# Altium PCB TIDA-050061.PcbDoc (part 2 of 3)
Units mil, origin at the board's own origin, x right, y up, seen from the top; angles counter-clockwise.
Board outline 3950.94 x 4411.21 mil, 8 copper layers (Top Layer, Layer 1, Layer 2, Layer 3, Layer 4, Layer 5, Layer 6, Bottom Layer), stack 61.2 mil thick; 178 components, 34 nets, 398 pads, 112 vias.
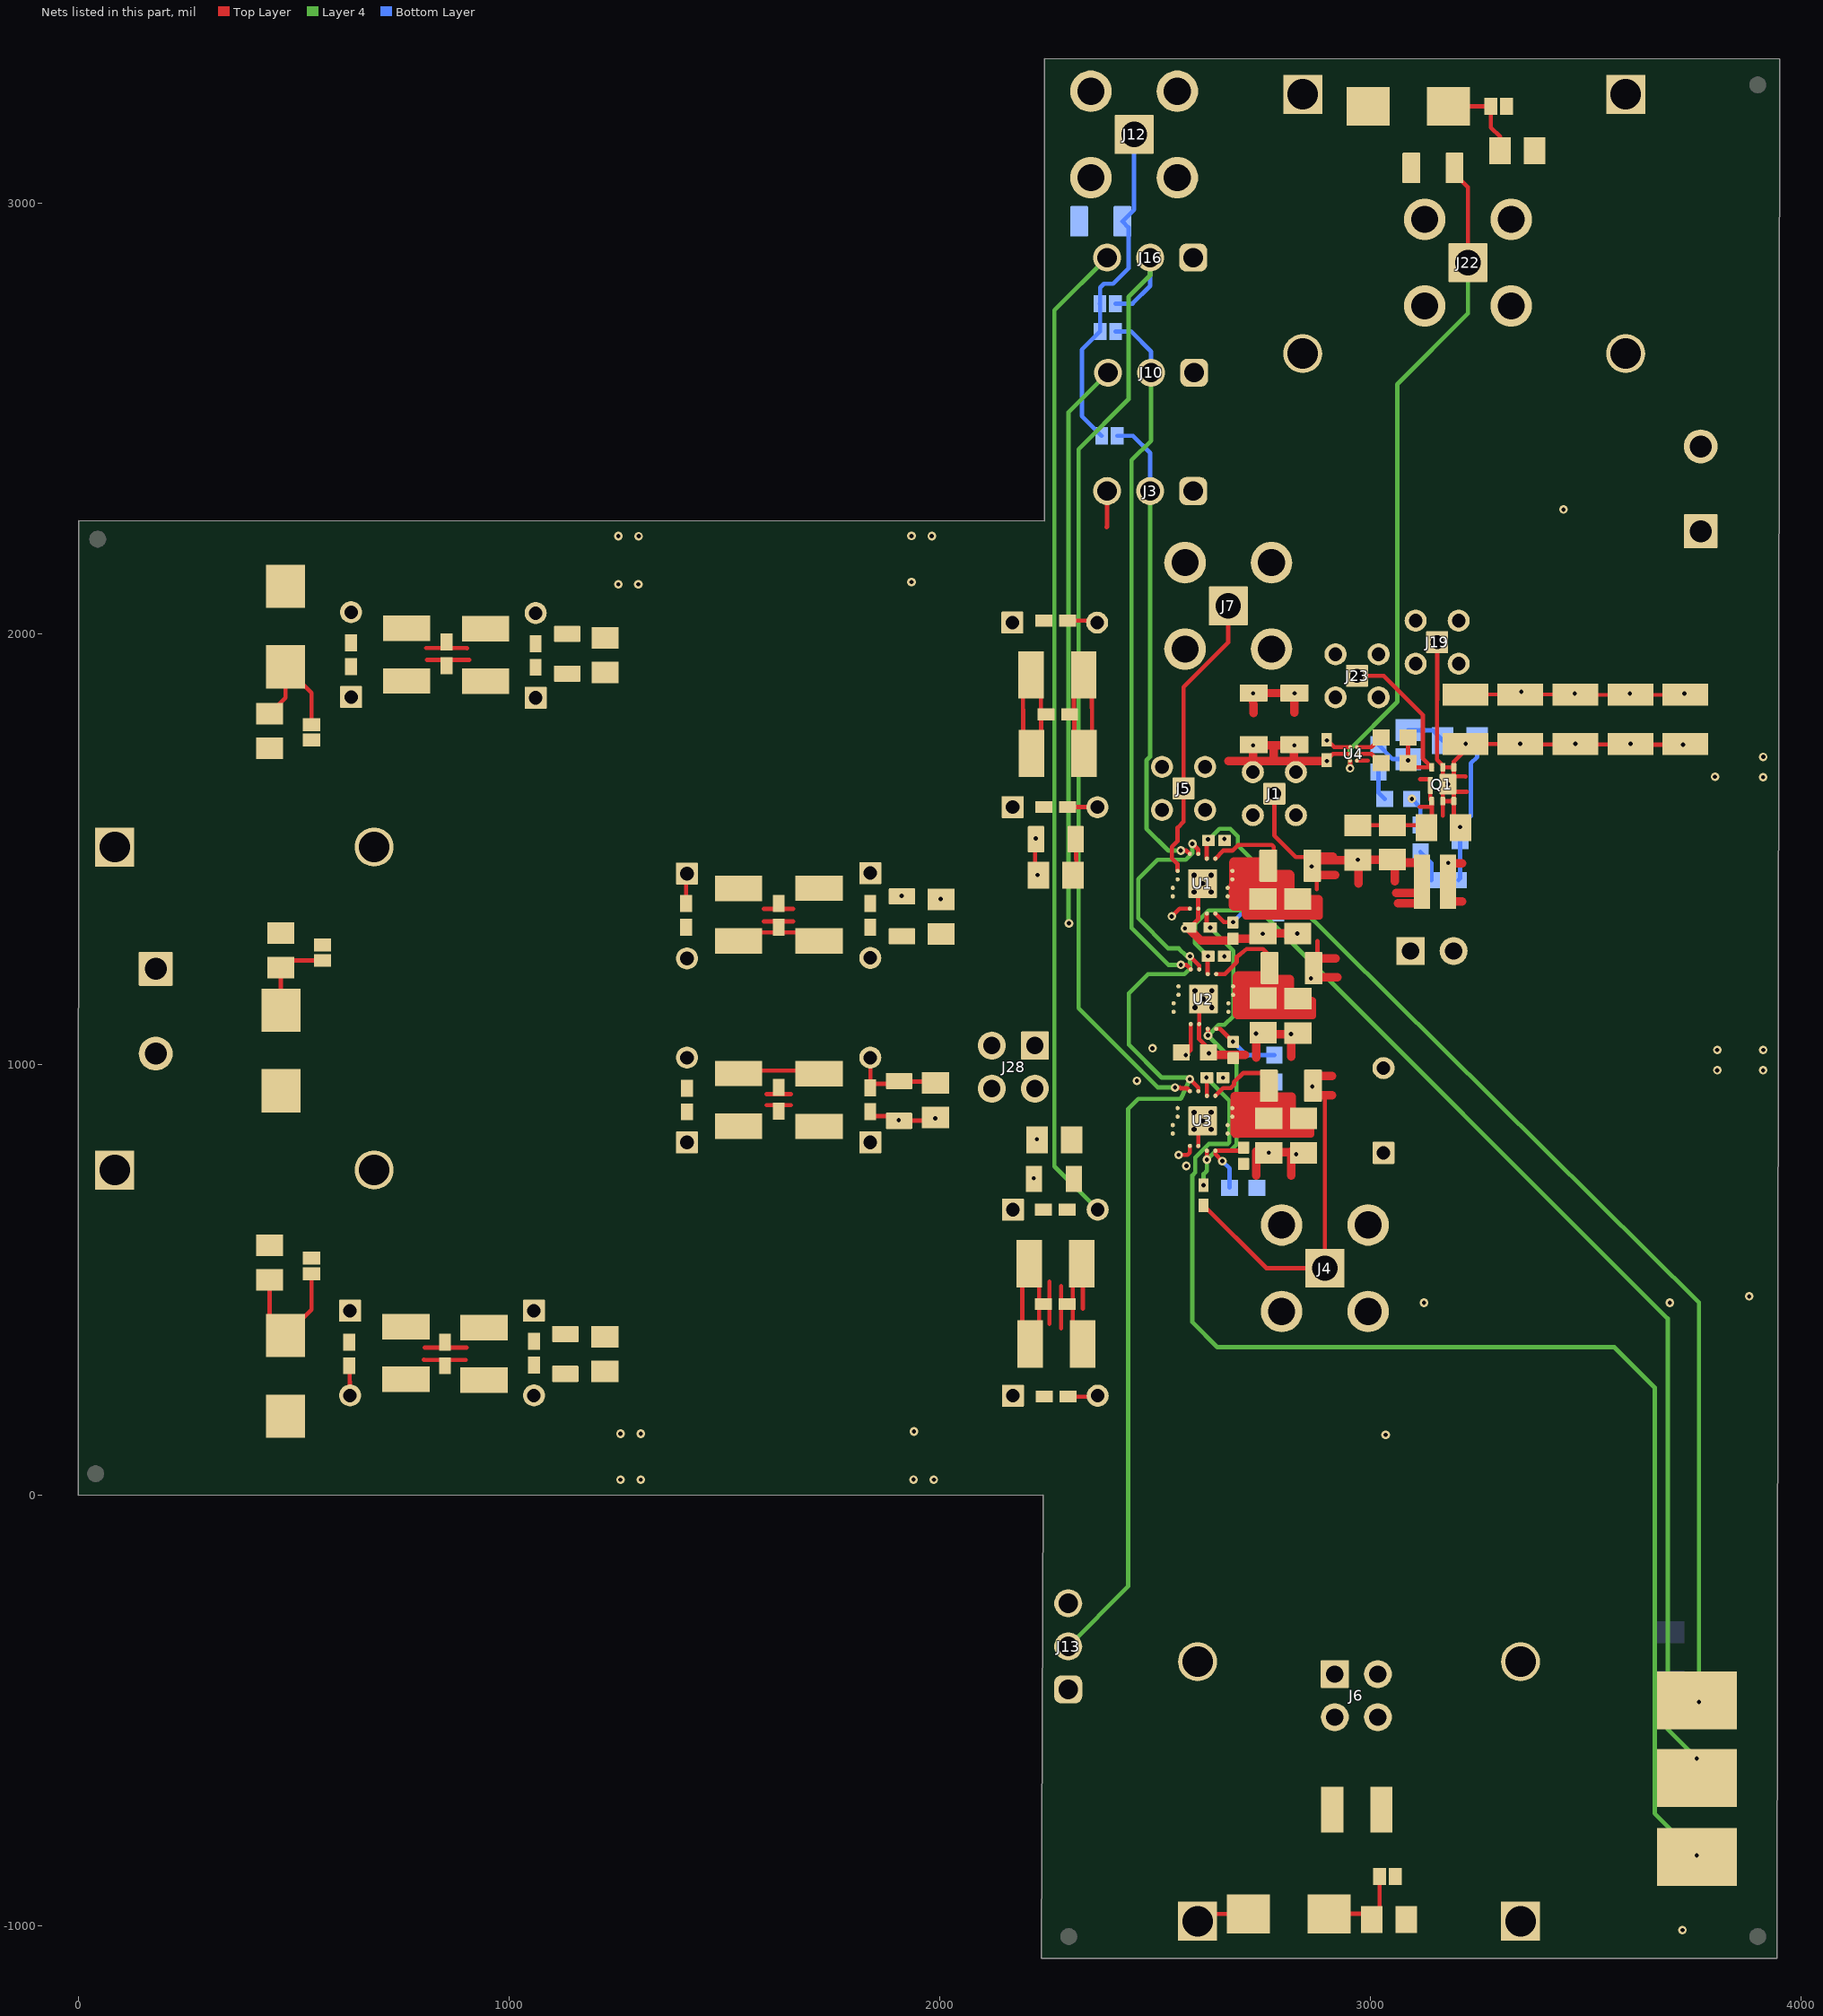
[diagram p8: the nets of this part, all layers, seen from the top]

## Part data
C1 C28 C29 C30 C31 C48 C49 C56 C57 C66 C67 C68 C69: library part CMP-0093206-1, "Cap Aluminum Polymer 560uF 20VDC 20% (10 X 13mm) Radial 5mm 0.012 Ohm 1700mA 1000h 125C", Digikey Part Number=P122095-ND, Leakage Current=2240uA, Manufacturer=Panasonic, Mouser Part Number=667-20SEF560M, Operating Temperature Range="-55°C to +125°C", Tolerance_%=20%, ValueDisplayed=560uF
C2: library part CMP-0081639-1, "CAP, CERM, 10 µF, 35 V,+/- 10%, X7R, 1210", Cap_Case=1210, Manufacturer=MuRata, Supplier Part Number 1=GRM32ER7YA106KA12K-ND, TempCo=X7R, Tolerance_%=10%, Value1="0.001 ohm", Value2=35V, ValueDisplayed=10µF
C3: library part CMP-0006949-4, "CAP, CERM, 4.7 uF, 10 V, +/- 10%, X5R, 0603", Cap_Case=0603, Manufacturer=Kemet, Supplier Part Number 1=399-5503-1-ND, TempCo=X5R, Tolerance_%=10%, Value1="0.006 ohm", Value2=10V, ValueDisplayed=4.7uF
C4 C5 C7 C11 C15: library part CMP-0008377-2, "CAP, CERM, 22 uF, 10 V, +/- 20%, X7R, 0805", Cap_Case=0805, Manufacturer=MuRata, Supplier Part Number 1=81-GRM21BZ71A226ME5L, TempCo=X7R, Tolerance_%=20%, Value1=Unknown, Value2=10V, ValueDisplayed=22uF
C6 C20 C26 C45 C64: library part CMP-0011645-1, "CAP, TA, 10 uF, 25 V, +/- 20%, 0.5 ohm, SMD", Cap_Case=C, Manufacturer=AVX, Supplier Part Number 1=478-1763-1-ND, Tolerance_%=20%, Value1="0.5 ohm", Value2=25V, ValueDisplayed=10uF
C8 C12 C16: library part CMP-0080705-2, "CAP, CERM, 2.2 µF, 25 V,+/- 10%, X7R, 0805", Cap_Case=0805, Manufacturer="Taiyo Yuden", Supplier Part Number 1=587-2991-1-ND, TempCo=X7R, Tolerance_%=10%, Value2=25V, ValueDisplayed=2.2µF
C9 C13 C17: library part CMP-0093200-1, "1µF ±10% 10V Ceramic Capacitor X7R 0402 (1005 Metric)", Digikey Part Number=2571-GMC04X7R105K10NTTR-ND, Manufacturer="Cal-Chip Electronics", Operating Temperature Range="-55°C to +125°C", TempCo=15%, Temperature Characteristic=X7R, Tolerance_%=10%, ValueDisplayed=1uF
C10 C14 C18: library part CMP-0064936-1, "CAP, CERM, 4.7 uF, 16 V,+/- 10%, X7R, 0603", Cap_Case=0603, Manufacturer=MuRata, TempCo=X7R, Tolerance_%=10%, Value1=Unknown, Value2=16V, ValueDisplayed=4.7uF
C19: library part CMP-0008040-1, "CAP, CERM, 1 pF, 100 V, +/- 5%, C0G/NP0, 0805", Cap_Case=0805, Manufacturer=MuRata, PartNumber=GQM2195C2A1R0CB01D, Supplier Part Number 1=490-3586-1-ND, TempCo=C0G/NP0, Tolerance_%=5%, Value1=Unknown, Value2=100V, ValueDisplayed=1pF
C21: library part CMP-0006297-2, "CAP, CERM, 0.1 uF, 50 V, +/- 10%, X7R, 0402", Cap_Case=0402, Manufacturer=TDK, Supplier Part Number 1=445-5932-1-ND, TempCo=X7R, Tolerance_%=10%, Value1="0.039064 ohm", Value2=50V, ValueDisplayed=0.1uF
C22 C23: library part CMP-0093201-1, "10 µF ±10% 50V Ceramic Capacitor X7R 1206 (3216 Metric)", Manufacturer="Cal-Chip Electronics", Operating Temperature Range="-55°C to +125°C", TempCo=15%, Temperature Characteristic=X7R, Tolerance_%=10%, ValueDisplayed=10uF
C24 C25: library part CMP-0006723-4, "CAP, CERM, 1000 pF, 100 V, +/- 5%, X7R, 0603", Cap_Case=0603, Manufacturer=AVX, Supplier Part Number 1=478-3698-1-ND, TempCo=X7R, Tolerance_%=5%, Value1="0.276 ohm", Value2=100V, ValueDisplayed=1000pF
C27 C38 C46 C47 C65 C76: library part CMP-0090082-1, "Cap Ceramic 4.7uF 50V X7R 10% Pad SMD 0805 +125°C Automotive T/R", Manufacturer="TDK Corporation", Operating Temperature Range="-55°C to +125°C", TempCo=15%, Temperature Characteristic=X7R, Tolerance_%=0.1%, ValueDisplayed=4.7uF
C32 C33 C39 C40 C50 C51 C58 C59 C70 C71 C77 C78: library part CMP-0080066-1, "CAP, CERM, 22 µF, 25 V,+/- 10%, X7R, 1210", Cap_Case=1210, Manufacturer="Samsung Electro-Mechanics", Supplier Part Number 1=1276-3391-1-ND, TempCo=X7R, Tolerance_%=10%, Value2=25V, ValueDisplayed=22µF
C34 C41 C52 C60 C72 C79: library part CMP-0079630-1, "CAP, CERM, 1 µF, 16 V,+/- 10%, X7R, AEC-Q200 Grade 1, 0805", Cap_Case=0805, Manufacturer=Kemet, Supplier Part Number 1=399-6930-1-ND, TempCo=X7R, Tolerance_%=10%, Value2=16V, ValueDisplayed=1µF
C35 C36 C37 C42 C43 C44 C53 C54 C55 C61 C62 C63 C73 C74 C75 C80 C81 C82: library part CMP-0860570-1, "CAP, CERM, 0.1 µF, 50 V,+/- 20%, X7R, 0402", Cap_Case=0402, Manufacturer="Taiyo Yuden", TempCo=X7R, Tolerance_%=20%, Value2=50V, ValueDisplayed=0.1µF
FID1 FID2 FID3 FID4 FID5 FID6 FID7 FID8 FID9 FID10: library part CMP-0077181-1, "Fiducial mark.  There is nothing to buy or mount.", Manufacturer=N/A
J1 J5 J19 J23: library part CMP-0096285-1, "MMCX Connector Jack, Female Socket 50Ohm Through Hole Solder", Dielectric Material=TEFLON, Digikey Part Number=2057-RF12-07H-T-00-50-G-ND, Manufacturer="Adam Tech", Operating Temperature Range=to
J2 J27: library part CMP-0055393-3, "Standard Banana Jack, insulated, 10A, red", Manufacturer="DEM Manufacturing", Supplier Part Number 1=30M0087
J3 J10 J13 J16: library part CMP-0054796-2, "Header, 2.54 mm, 3x1, Gold, TH", Color=Black, Manufacturer="Wurth Elektronik", Supplier Part Number 1=732-5316-ND
J4 J7 J12 J22: library part CMP-0096117-1, "SMA Connector Jack, Female Socket 50Ohm Through Hole Solder", Dielectric Material=PTFE, Digikey Part Number=2057-RF2-04A-T-00-50-G-ND, Frequency_Fixed=6GHz, Manufacturer="Adam Tech", Operating Temperature Range="-65°C to +165°C", Voltage_V=500V
J6 J28: library part CMP-0075404-1, "Header, 100mil, 2x2, Gold, TH", Color=Black, Current_A=6.3A, Manufacturer=Samtec, Supplier Part Number 1=SAM1028-02-ND, Voltage_V=550V
J8 J14 J15 J17 J20 J24 J26 J29 J32: library part CMP-0003883-1, "Jumper, SMT", Manufacturer=Any
J9 J31: library part CMP-0055389-3, "Standard Banana Jack, insulated, 10A, black", Manufacturer="DEM Manufacturing", Supplier Part Number 1=45M6896
J11 J30: library part CMP-0087503-1, "TERM BLK 2POS SIDE ENTRY 5MM PCB", Current_A=16A, Manufacturer="Würth Elektronik", Voltage_V=300V
J18: library part CMP-0054566-1, "Header, 100mil, 2x1, Gold, TH", Color=Black, Current_A=3A, Manufacturer="Sullins Connector Solutions", Supplier Part Number 1=S1011E-02-ND, Voltage_V=1.8kV
J21: library part CMP-0055393-3, "Standard Banana Jack, insulated, 10A, red", Manufacturer="DEM Manufacturing", PartNumber=571-0500, Supplier Part Number 1=30M0087
J25: library part CMP-0055389-3, "Standard Banana Jack, insulated, 10A, black", Manufacturer="DEM Manufacturing", PartNumber=571-0100, Supplier Part Number 1=45M6896
LOGO1: library part CMP-0074837-1, "IEC 61010-1 Hot Surface Warning"
Logo2: library part CMP-0074844-1
Logo4: library part CMP-0074847-1, "FCC_disclaimer"
Logo5: library part CMP-0074769-1
MP1: library part CMP-0095762-1, "Thermal Pad White 19.05mm x 6.35mm Rectangular Adhesive - Both Sides", Digikey Part Number=19.05MM-6.35MM-25-8810-ND, Manufacturer=3M, Operating Temperature Range=to
MP2: library part CMP-0096629-1, "Heatsink, 46 K/W, 19x6.3x4.8 mm, black anodized", Digikey Part Number=AE10818-ND, Manufacturer="Assmann WSW Components", Natural Thermal Resistance=46°C/W, Operating Temperature Range=to
Q1: library part CMP-0095537-1, "40 V optiMOS Power Transistor, Surface Mount 6-PQFN Dual (2x2)", Digikey Part Number=448-ISK024NE2LM5AULA1CT-ND, Drain To Source Breakdown Voltage=25V, Input Capacitace At Vds="960pF @ 12V", Manufacturer=Infineon, Mouser Part Number=726-ISK024NE2LM5AULA, Operating Temperature Range="-55°C to +150°C", Power_W=2.1W, Pulse Drain Current=221A, Typ Forward Diode Voltage=0.81V
R1 R4 R7: library part CMP-0095593-1, "Fixed Resistor, Metal Alloy, 1W, 0.0025ohm, 1% +/-Tol, 50ppm/Cel, Surface Mount, 1206", Manufacturer=Welwyn, Mouser Part Number=756-ULR1S-R0025FT2, Operating Temperature Range="-55°C to +170°C", Power_W=1W, TempCo=50ppm/°C, Tolerance_%=1%
R2 R5 R8: library part CMP-0092204-1, "100 kOhms ±1% 0.063W, 1/16W Chip Resistor 0402 (1005 Metric)  Thick Film", Digikey Part Number=541-3960-1-ND, Manufacturer=Vishay, Mouser Part Number=71-CRCW0402100KFKEDC, Operating Temperature Range="-55°C to +155°C", Power_W=63mW, TempCo=100ppm/°C, Tolerance_%=1%
R3 R24 R26 R27 R28: library part CMP-0074786-1, "RES, 1.00, 1%, 0.333 W, AEC-Q200 Grade 1, 0805", Manufacturer=Panasonic, Power_W=333mW, Supplier Part Number 1=P17499CT-ND, TempCo="200 ppm/C", Tolerance_%=1%, Value2=0.333W, Value_Code=1R00, ValueDisplayed=1.00
R6 R10: library part CMP-0026414-2, "RES, 4.99 k, 1%, 0.063 W, AEC-Q200 Grade 0, 0402", Manufacturer=Vishay-Dale, Power_W=63mW, Supplier Part Number 1=541-4.99KLCT-ND, TempCo="100 ppm/C", Tolerance_%=1%, Value2=0.063W, Value_Code=4k99, ValueDisplayed=4.99k
R9 R25: library part CMP-0093196-1, "RES Thick Film, 49.9Ω, 1%, 0.75W, 100ppm/°C, 1206", Manufacturer="Vishay Dale", Operating Temperature Range="-55°C to +155°C", Power_W=750mW, TempCo=100ppm/°C, Tolerance_%=1%
R11: library part CMP-0084633-1, "RES, 0.005, 1%, 0.5 W, AEC-Q200 Grade 0, 1206", Manufacturer=Vishay-Dale, Power_W=500mW, TempCo="110 ppm/C", Tolerance_%=1%, Value2=0.5W, Value_Code=5L000, ValueDisplayed=0.005
R12: library part CMP-0015056-3, "RES, 0.05, 1%, 1 W, AEC-Q200 Grade 0, 0612", Manufacturer=Panasonic, Power_W=1W, Supplier Part Number 1=P18935CT-ND, TempCo="150 ppm/C", Tolerance_%=1%, Value_Code=R050, ValueDisplayed=0.05
R13 R14 R15 R16 R17: library part CMP-0082786-1, "RES, 154, 1%, 0.5 W, 1210", Manufacturer=Yageo, Power_W=500mW, TempCo="100 ppm/C", Tolerance_%=1%, Value2=0.5W, Value_Code=154R, ValueDisplayed=154
R18: library part CMP-0020616-3, "RES, 0, 5%, 0.125 W, AEC-Q200 Grade 0, 0805", Manufacturer=Panasonic, Power_W=125mW, Supplier Part Number 1=P0.0ACT-ND, TempCo="600 ppm/C", Tolerance_%=5%, Value2=0.125W, Value_Code=0000, ValueDisplayed=0
R19 R20: library part CMP-0022906-5, "RES, 20.0 k, 1%, 0.1 W, 0603", Manufacturer=Yageo, Power_W=100mW, Supplier Part Number 1=311-20.0KHRCT-ND, TempCo="100 ppm/C", Tolerance_%=1%, Value2=0.1W, Value_Code=20k0, ValueDisplayed=20.0k
R21: library part CMP-0021519-3, "RES, 1.00 k, 1%, 0.125 W, AEC-Q200 Grade 0, 0805", Manufacturer=Panasonic, Power_W=125mW, Supplier Part Number 1=P1.00KCCT-ND, TempCo="100 ppm/C", Tolerance_%=1%, Value2=0.125W, Value_Code=1k00, ValueDisplayed=1.00k
R22 R23: library part CMP-0023343-3, "RES, 0, 1%, 0.1 W, AEC-Q200 Grade 0, 0603", Manufacturer="Stackpole Electronics Inc", Power_W=100mW, Supplier Part Number 1=RMCF0603ZT0R00CT-ND, TempCo=ppm/C, Tolerance_%=1%, Value2=0.1W, Value_Code=0
SH-J1 SH-J2 SH-J3 SH-J4: library part CMP-0003623-3, "Shunt, 100mil, Gold plated, Black", Alternate Manufacturer=3M, Alternate PartNumber=969102-0000-DA, Manufacturer=Samtec, Supplier Part Number 1=SAM8858-ND
TP1 TP2 TP3: library part CMP-0055153-1, "Test Point, Compact, SMT", Manufacturer=Keystone, Supplier Part Number 1=36-5016TR-ND
U1 U2 U3: library part CMP-0090637-2, "5-A, Low-VIN (0.7V), Low-Noise, High-Accuracy, Ultra-Low Dropout (LDO) Voltage Regulator", Dropout Voltage=100mV, Manufacturer="Texas Instruments", Max Supply Voltage=6V, Min Supply Voltage=700mV, Nominal Supply Current=10mA, Operating Temperature Range="-40°C to +125°C", Output Voltage=0.5-5.2V
U4: library part CMP-0084842-1, "5V, 7A/5A Low Side GaN Driver With 60MHz/1ns Speed, YFF0006AEAE (DSBGA-6)", Alternate Manufacturer="Texas Instruments", Alternate PartNumber=LMG1020YFFT, Operating Temperature Range="-40 to 125 C", Rating=Catalog
ZZ1: library part CMP-0077236-1
ZZ2: library part CMP-0077237-1
ZZ3: library part CMP-0077238-1
ZZ4 ZZ5 ZZ6 ZZ7 ZZ8: library part CMP-0077238-1, "The tab route width shall be between 80 mils and 120 mils"

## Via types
v1: diameter 20, hole 10, Top Layer to Bottom Layer, 97 vias
v2: diameter 23.62, hole 11.81, Top Layer to Bottom Layer, 15 vias

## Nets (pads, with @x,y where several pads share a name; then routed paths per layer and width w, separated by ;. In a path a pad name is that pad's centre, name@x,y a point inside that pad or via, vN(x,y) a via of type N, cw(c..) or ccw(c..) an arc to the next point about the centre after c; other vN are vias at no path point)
BIAS: C2.1 C3.1 C6.1 J2.1 J2.2 J6.1 J6.3 R2.1 R5.1 R8.1 U1.5 U2.5 U3.5 | length 268
  Top Layer w10: v1(2539.12,1344.04) 2557.07,1361.99 U1.5@2581.01,1361.99 ; v1(2555.13,790.07) 2575.98,790.07 2581.35,795.45 U3.5@2581.35,811.19 ; v1(2571.74,1022.08) 2583.2,1033.54 U2.5@2583.2,1094.01 ; J2.1@2589.99,-972.33 C6.1@2687.79,-972.4
  other v1: 2658.06,969.37 2661.36,1251.35 2661.53,1523.86
CP_EN: J13.2 U1.15 U2.15 U3.15 | length 2502.2
  Top Layer w10: v1(2580.96,966.35) 2601.04,946.27 U3.15@2601.04,938.16 U3.15@2600.78,938.42 ; v1(2581.38,1251.59) 2602.89,1230.09 U2.15@2602.89,1220.98 ; v1(2587.1,1512.63) 2600.69,1499.03 2600.69,1488.96 U1.15@2600.14,1489.5
  Layer 4 w10: J13.2@2298.69,-351.13 2437.86,-211.96 2437.86,896.81 2461.49,920.44 2559.95,920.44 v1(2580.96,966.35) 2577.59,969.72 2560.15,969.72 2516.03,969.61 2439.61,1046.03 2439.61,1165.52 2483.41,1209.32 2568.61,1209.92 2581.38,1222.7 v1(2581.38,1251.59) 2573.64,1251.59 2555.42,1269.81 2530.69,1269.81 2461.49,1339.81 2461.49,1430.8 2506.44,1475.75 2571.83,1475.75 2587.1,1491.01 v1(2587.1,1512.63)
EN_1: J3.2 J14.1 U1.16 | length 1094.1
  Top Layer w10: v1(2559.95,1496.98) 2572.98,1496.98 U1.16@2581.01,1488.96
  Layer 4 w10: J3.2@2488.97,2331.8 2488.97,1714.9 2480.41,1706.34 2480.41,1547.63 2531.06,1496.98 v1(2559.95,1496.98)
  Bottom Layer w10: J14.1@2412.37,2460 2449.24,2460 2488.97,2420.27 J3.2@2488.97,2331.8
EN_2: J10.2 J15.1 U2.16 | length 1636.4
  Top Layer w10: v1(2560.15,1231.44) 2572.74,1231.44 U2.16@2583.2,1220.98
  Layer 4 w10: J10.2@2491.25,2606.66 2491.25,2448.76 2445.86,2403.36 2445.86,1316.85 2531.26,1231.44 v1(2560.15,1231.44)
  Bottom Layer w10: J15.1@2408.69,2702.4 2444.22,2702.4 2491.25,2655.37 J10.2@2491.25,2606.66
EN_3: J16.2 J17.1 U3.16 | length 2302.7
  Top Layer w10: 2558.02,946.78 2559.93,944.87 2574.65,944.87 U3.16@2581.35,938.16
  Layer 4 w10: J16.2@2488.97,2873.82 2488.97,2832.64 2438.97,2782.64 2438.97,2545 2322.61,2428.64 2322.61,1131.03 2506.86,946.78 v1(2546.89,946.78)
  Bottom Layer w10: J17.1@2408.19,2767.07 2448.03,2767.07 2488.97,2808.01 J16.2@2488.97,2873.82
GND: C1.1 C2.2 C3.2 C4.2 C5.2 C7.2 C8.2 C9.1 C10.2 C11.2 C12.2 C13.1 C14.2 C15.2 C16.2 C17.1 C18.2 C21.2 C22.1 C23.1 C24.2 C25.2 C27.1 C28.1 C29.1 C30.1 C31.1 C32.2 C33.2 C34.2 C35.2 C36.2 C37.2 C38.1 C39.2 C40.2 C41.2 C42.2 C43.2 C44.2 C46.1 C47.1 C48.1 C49.1 C50.2 C51.2 C52.2 C53.2 C54.2 C55.2 C56.1 C57.1 C58.2 C59.2 C60.2 C61.2 C62.2 C63.2 C65.1 C66.1 C67.1 C68.1 C69.1 C70.2 C71.2 C72.2 C73.2 C74.2 C75.2 C76.1 C77.2 C78.2 C79.2 C80.2 C81.2 C82.2 J1.2 J1.3 J1.4 J1.5 J3.1 J4.2 J4.3 J4.4 J4.5 J5.2 J5.3 J5.4 J5.5 J6.2 J6.4 J7.2 J7.3 J7.4 J7.5 J8.1 J9.1 J9.2 J10.1 J11.2 J12.2 J12.3 J12.4 J12.5 J13.1 J16.1 J19.2 J19.3 J19.4 J19.5 J22.2 J22.3 J22.4 J22.5 J23.2 J23.3 J23.4 J23.5 J24.1 J25.1 J25.2 J26.1 J28.2 J28.4 J29.1 J30.1 J31.1 J31.2 J32.1 Q1.4 R3.1 R9.1 R10.1 R21.1 R24.1 R25.1 R26.1 R27.1 R28.1 U1.6 U1.17 U2.6 U2.17 U3.6 U3.17 U4.B1 U4.C2 | length 3021.3
  Top Layer w10: 803.86,342.57 901.65,342.49 ; 809.47,1939.56 907.36,1939.41 ; C57.1@1411.18,1438.19 C63.2@1411.4,1371.75 ; 1592.15,1361.37 1660.05,1361.24 ; 1598.04,905.64 1654.55,905.64 ; C53.2@1836.06,880.2 C46.1@1892.57,880.2 ; C46.1@1921.93,870.06 C52.2@1978.45,870.06 ; C70.2@2192.16,387.63 C71.2@2192.24,485.43 ; C33.2@2193.68,1875.05 2194.3,1777.97 ; C27.1@2221.6,1518.76 C34.2@2222.21,1421.68 ; C70.2@2231.16,394.87 C71.2@2231.24,492.67 ; C33.2@2235.46,1861.61 C32.2@2236.08,1764.53 ; 2255.04,398.13 2255.12,495.93 ; R10.1@2581.01,1318.16 2600.69,1337.85 2600.69,1361.99 2600.69,1390.53 U1.17@2590.85,1400.37 ; U3.6@2599.93,810.09 U3.6@2601.04,811.19 2601.04,859.42 v2(2610.88,869.27) ; U2.6@2601.94,1093.06 U2.6@2602.69,1093.82 ; v2(2612.73,1152.08) 2602.89,1142.24 U2.6@2602.89,1094.01 ; C3.2@2637.44,1028.42 2633.26,1028.42 2602.69,1058.98 U2.6@2602.69,1093.82 ; v1(2728.14,1741.22) C22.1@2728.19,1741.26 ; C7.2@2738.13,1292.26 C7.2@2750.48,1304.6 ; C21.2@2899.21,1706.91 2913.7,1721.4 U4.B1@2953.46,1721.4 ; U4.C2@2969.21,1705.65 2994.79,1705.65 2994.9,1705.77 ; C5.2@2974.13,1555.75 3056.27,1555.75 3121.87,1555.75 3128.55,1549.07 3142.96,1563.48 Q1.4@3142.96,1611.62 3139.61,1614.96 Q1.4@3139.61,1648.03 ; 3114.79,1598.69 3139.57,1598.56 ; 3115.44,1662.74 Q1.4@3140.22,1662.6 ; U2.6@2602.69,1093.82 2602.69,1094.01 U2.6@2602.89,1094.01 ; U2.6@2602.69,1093.82 U2.6@2602.89,1094.01
  Top Layer w20: R10.1@2580.69,1313.94 2606.59,1288.04 C9.1@2681.05,1288.04 ; C3.2@2628.41,1022.6 2709.39,1022.6 ; 2671.07,1704.94 2727.94,1704.94 ; C9.1@2681.36,1292.26 C7.2@2738.13,1292.26 ; C22.1@2727.64,1746.72 2727.67,1742.88 2727.68,1741.22 2727.94,1704.94 ; J1.2@2727.96,1701.51 2727.94,1704.94 ; C22.1@2728.19,1741.26 C23.1@2822.92,1741.26 ; C15.2@2735.14,798.5 2735.14,796.61 2735.14,796.3 2735.29,742.74 ; C11.2@2735.13,1071.59 2735.29,1015.84 ; C15.2@2737.38,796.62 C16.2@2816,796.44 ; C7.2@2750.48,1304.6 C8.2@2831.46,1304.6 ; C11.2@2758.01,1070.17 C12.2@2832.53,1070.17 ; 2776.03,1738.78 2776.24,1708.71 ; C16.2@2816.56,798.5 2816.57,796.62 2816.57,796.44 2816.72,742.74 ; C12.2@2816.57,1074.28 2816.57,1072.72 2816.58,1070.73 2816.72,1018.52 ; C23.1@2822.89,1744.43 2822.9,1742.88 C23.1@2822.92,1741.26 ; J1.3@2823.22,1699.22 2823.18,1704.94 ; v1(2824.05,1741.26) C23.1@2822.92,1741.26 ; C21.2@2896.36,1704.94 2823.18,1704.94 ; 2727.94,1704.94 2823.18,1704.94 ; C23.1@2822.92,1741.26 2823.18,1704.94
  Bottom Layer w10: v1(3096.62,1616.89) 3116.76,1596.75 C25.2@3116.76,1556.6
  other v1: 3725.34,-1009.81 3035.84,140 2218.49,735.95 2573.17,764.6 2828.01,791.89 2764.65,795.2 2225.8,826.48 1905.21,870.81 1989.82,875.34 2458.41,962.39 2625.63,1026.39 2494.37,1037.72 2815.89,1070.73 2734.62,1071.7 2750.15,1303.69 2830.78,1304.33 2569.51,1316.08 2002.71,1384.51 1912.02,1391.8 2227.5,1440.23 2223.24,1524.84 2899.16,1704.79
  other v2: 2591.2,849.58 2630.57,849.58 2591.2,888.95 2630.57,888.95 2593.04,1132.4 2632.41,1132.4 2593.04,1171.77 2632.41,1171.77 2591.2,1400.48 2630.57,1400.48 2610.88,1420.16 2591.2,1439.85 2630.57,1439.85
NetC6_2: C6.2 J8.2 R3.2 | length 212.1
  Top Layer w10: C6.2@2904.38,-972.12 2990.17,-972.12 R3.2@3003.37,-985.32 3021.92,-966.76 J8.2@3021.92,-885.32
NetC7_1: C7.1 C8.1 R1.1 U1.9 U1.10 U1.11 U1.12 U1.13 | length 1715.3
  Top Layer w10: U1.13@2640.06,1478.13 2658.59,1496.66 2680.16,1496.66 2693.35,1509.85 2771.76,1509.85 2775.76,1505.85 2775.76,1474.3 R1.1@2763.37,1461.91 ; R1.1@2763.28,1461.82 R1.1@2763.37,1461.91 ; R1.1@2772.2,1470.74 R1.1@2763.37,1461.91
  Top Layer w15: 2711.1,1344.04 2882.37,1344.04 ; 2882.37,1344.62 2882.37,1384.6
  Top Layer w20: 2683.66,1471.39 R1.1@2745.31,1471.56 ; C7.1@2751.1,1384.04 C7.1@2751.41,1384.04 ; 2751.41,1347.15 C7.1@2751.41,1384.04 ; C7.1@2751.41,1388.38 C7.1@2751.41,1384.04 ; 2760.08,1418.09 2761.13,1418.1 ; C7.1@2760.4,1390.38 C8.1@2811.42,1390.51 ; C7.1@2761.13,1375.18 C7.1@2761.13,1384.06 ; R1.1@2761.13,1469.93 R1.1@2761.13,1461.91 ; R1.1@2763.26,1476.98 R1.1@2769.3,1476.99 ; R1.1@2763.87,1461.91 2763.37,1461.91 R1.1@2761.13,1461.91 ; 2809.59,1418.47 2763.61,1418.11 2761.13,1418.1 ; 2831.78,1347.71 C8.1@2831.77,1384.24 ; C8.1@2831.77,1388.95 2831.77,1384.6 C8.1@2831.77,1384.24 ; 2879.73,1384.36 C8.1@2831.77,1384.24 ; C7.1@2751.41,1384.04 C7.1@2761.13,1384.06 ; C7.1@2761.13,1384.06 2812.15,1384.19 2831.46,1384.24 C8.1@2831.77,1384.24 ; C7.1@2761.13,1384.06 2761.13,1418.1 ; 2761.13,1418.1 2761.13,1440.13 R1.1@2761.13,1461.91
  Top Layer w25: 2684.31,1469.36 2684.34,1449.59 U1.11@2684.37,1429.91 ; U1.11@2684.37,1429.87 2684.23,1410.1 2684.09,1390.42 2683.94,1370.26 2712.16,1370.25 ; U1.12@2684.51,1449.55 2684.53,1451.44 ; 2696.93,1374.13 2697.01,1452.08 ; 2713.56,1349.14 2713.48,1383.95 2713.48,1384.08 2713.56,1461.91 ; C7.1@2732.71,1384.7 2732.79,1461.85 2732.79,1462.66 ; C7.1@2742.22,1378.48 2742.23,1384.05 2742.3,1456.44 ; R1.1@2757.3,1440.15 2761.13,1440.13 2763.18,1440.12 2812.09,1439.9 2812.15,1384.59 2812.15,1384.19 C8.1@2812.15,1382.76
  Top Layer w30: 2714.46,1402.98 2799.42,1401.57 ; C7.1@2728.56,1363.28 2870.83,1362.48
NetC11_1: C11.1 C12.1 R4.1 U2.9 U2.10 U2.11 U2.12 U2.13 | length 1428.5
  Top Layer w10: U2.13@2642.26,1210.15 2662.65,1210.15 2690.32,1238.38 2690.32,1249.81 2712.73,1268.41 2751.1,1268.41 2766.38,1253.13 R4.1@2766.38,1223.9 ; R4.1@2752.78,1247.81 R4.1@2756.66,1251.69
  Top Layer w15: 2691.66,1112.93 2867.19,1112.64 2867.19,1148.76
  Top Layer w20: 2691.25,1192.58 2692.81,1192.61 R4.1@2756.99,1193.6 ; 2692.8,1193.64 2692.8,1206.34 R4.1@2756.99,1206.4 ; 2698.48,1179.46 2753.84,1179.46 ; 2702.61,1144.49 C11.1@2757.97,1144.49 ; 2735.14,1115.78 2735.13,1151.59 2735.13,1152.67 C11.1@2735.13,1154.9 ; C11.1@2756.99,1136.69 2756.99,1152.67 R4.1@2756.99,1193.6 ; R4.1@2756.99,1231.44 R4.1@2756.99,1206.4 ; 2758.25,1183.8 2766.68,1183.86 2807.75,1184.18 ; R4.1@2759.68,1193.64 R4.1@2756.99,1193.6 ; R4.1@2762.32,1198.46 2766.57,1198.5 2811.83,1198.84 ; R4.1@2767.38,1206.41 2766.39,1206.41 R4.1@2756.99,1206.4 ; C12.1@2813.48,1164.86 2813.77,1198.45 ; 2815.94,1116.1 2815.94,1150.59 C12.1@2815.93,1154.94 ; C12.1@2834.88,1147.1 2864.35,1147.21 ; R4.1@2756.99,1193.6 R4.1@2756.99,1206.4
  Top Layer w25: 2693.09,1203.66 2692.8,1193.64 2692.81,1192.61 2692.93,1181.73 2693.14,1162.05 2693.26,1151.14 2693.38,1118.21
  Top Layer w30: 2698.51,1169.32 C12.1@2815.83,1164.19 ; 2707.82,1131.92 C12.1@2850.08,1131.12 ; C11.1@2728.61,1152.67 2735.13,1152.67 2756.99,1152.67 C12.1@2803.97,1152.67
NetC15_1: C15.1 C16.1 R7.1 U3.9 U3.10 U3.11 U3.12 U3.13 | length 1529.4
  Top Layer w10: U3.13@2640.41,927.34 2658.57,945.5 2676.26,945.5 2683.65,952.89 2683.65,958.61 2705.6,980.56 2750.68,980.56 R7.1@2750.71,980.53 ; 2680.26,873.84 2680.26,926.43 ; 2680.54,839.78 2680.54,870.68 ; 2709.11,927.34 2710.38,926.06 ; C15.1@2734.5,874.58 C15.1@2736.54,876.62 ; R7.1@2748.75,966.76 R7.1@2764.72,950.79
  Top Layer w15: 2685.8,836.97 2862.44,837.67 ; 2862.44,838.8 C16.1@2862.64,878.8
  Top Layer w20: 2685.37,926.59 R7.1@2754.22,927.08 ; 2687.25,910.62 2756.75,910.62 ; 2710.34,926.39 2710.72,876.89 ; C15.1@2735.51,892.16 2735.89,842.65 ; R7.1@2756.55,936.14 2756.75,910.62 ; C15.1@2756.93,886.64 2756.93,886.93 2756.75,910.62 ; 2765.95,907.55 2807.02,907.86 ; R7.1@2766.37,925.49 2815.88,925.87 ; C16.1@2816.93,892.16 2817.31,842.65 ; 2817.46,925.62 C16.1@2817.84,876.12 ; C16.1@2828.45,877.18 C16.1@2859.63,877.15
  Top Layer w25: 2693.07,923.43 2693.46,842.16
  Top Layer w30: 2707.82,848.91 2850.08,848.11 ; 2707.82,862.66 C16.1@2850.08,861.86 ; 2710.63,888.95 C16.1@2827.95,883.82 ; C15.1@2741.54,876.62 C16.1@2816.9,876.62
NetC19_1: C19.1 R18.1 | length 90.3
  Bottom Layer w10: C19.1@3088.21,1776.32 3144.42,1776.32 R18.1@3168.55,1752.19
NetC19_2: C19.2 J23.1 Q1.3 R19.2 R20.2 R22.2 | length 537.7
  Top Layer w10: J23.1@2969.42,1902.61 3031.55,1902.61 3122.24,1811.92 3122.24,1711.07 Q1.3@3142.96,1690.36 3097.54,1690.36 R20.2@3088.21,1699.68 ; R20.2@3078.55,1690.02 R20.2@3088.21,1699.68 ; R20.2@3085.53,1687.73 R20.2@3087.98,1687.69 ; R19.2@3088.21,1759.68 R20.2@3088.21,1699.68
  Bottom Layer w10: R22.2@3019.42,1742.4 3052.43,1709.39 C19.2@3088.21,1709.39
  other v1: 3088.14,1706.55
NetC20_2: C20.2 J24.2 R24.2 | length 210.4
  Top Layer w10: C20.2@3181.91,3225.18 J24.2@3280.33,3225.18 3280.33,3176.05 3301.64,3154.74 R24.2@3301.64,3122.07
NetC24_1: C24.1 R22.1 | length 68.4
  Bottom Layer w10: R22.1@3019.42,1679.41 3019.42,1631.1 C24.1@3033.62,1616.89
NetC25_1: C25.1 R23.1 | length 75.7
  Bottom Layer w10: C25.1@3116.76,1493.6 3142.05,1468.31 R23.1@3142.05,1428.35
NetC26_2: C26.2 J26.2 R26.2 | length 283.5
  Top Layer w10: R26.2@443.89,1814.35 481.02,1851.48 C26.2@481.02,1923.42 541.39,1863.05 J26.2@541.39,1789.35
NetC45_2: C45.2 J29.2 R27.2 | length 202.9
  Top Layer w10: C45.2@470.18,1126.27 R27.2@470.18,1225.56 486.43,1241.81 J29.2@567.02,1241.81
NetC64_2: C64.2 J32.2 R28.2 | length 313.5
  Top Layer w10: R28.2@443.89,499.96 443.89,407.5 C64.2@480.8,370.59 541.39,431.17 J32.2@541.39,514.37
NetJ12_1: J12.1 J14.2 J15.2 J17.2 R9.2 | length 793.7
  Bottom Layer w10: J14.2@2376.37,2460 2330.41,2505.97 2330.41,2660.11 J15.2@2372.69,2702.4 2372.69,2766.57 J17.2@2372.19,2767.07 2372.69,2767.56 2372.69,2804.31 2381.66,2813.28 2381.7,2813.24 2402.85,2813.24 2438.69,2849.08 2438.69,2943.76 R9.2@2424.46,2957.99 2451.7,2985.23 J12.1@2451.7,3159.79
NetJ18_2: J18.2 J19.1 J20.2 Q1.1 Q1.2 Q1.5 Q1.6 Q1.7 R12.1 R13.1 R14.1 R15.1 R16.1 R17.1 R18.2 R21.2 | length 1512.3
  Top Layer w10: J19.1@3155.53,1980.87 3155.23,1707.73 3168.55,1694.41 Q1.2@3168.55,1690.36 ; 3168.55,1577.62 Q1.5@3168.55,1611.62 ; Q1.7@3196.49,1669.21 3221.27,1669.07 ; 3200.31,1633.67 3225.1,1633.53 ; R21.2@3208.55,1549.07 3194.14,1563.48 Q1.6@3194.14,1611.62 ; R17.1@3221.52,1744.46 3221.75,1744.46 3348.45,1743.98 3348.68,1743.98 3476.22,1743.5 3476.45,1743.5 3604.67,1743.01 3604.9,1743.01 v1(3726.65,1742.54) ; R17.1@3226.22,1735.15 3194.14,1703.07 Q1.1@3194.14,1690.36 ; Q1.5@3168.55,1611.62 3168.55,1639.17 v1(3180.36,1650.99) ; Q1.5@3168.55,1611.62 Q1.6@3194.14,1611.62 ; Q1.2@3168.55,1690.36 3168.55,1662.8 v1(3180.36,1650.99) ; Q1.2@3168.55,1690.36 Q1.1@3194.14,1690.36 ; v1(3180.36,1650.99) 3194.14,1637.21 Q1.6@3194.14,1611.62 ; v1(3180.36,1650.99) 3194.14,1664.77 Q1.1@3194.14,1690.36
  Top Layer w20: R12.1@3184.26,1467.16 3212.93,1467.23 ; R12.1@3188.33,1378.59 3213.61,1378.65
  Bottom Layer w10: v1(3208.55,1551.6) 3233.64,1576.7 3233.64,1699.33 3248.55,1714.24 R18.2@3248.55,1752.19
  other v1: 3180.97,1468.31 3221.75,1744.67 3348.68,1744.72 3476.46,1744.72 3604.9,1744.72
NetJ20_1: J20.1 R23.2 | length 88.7
  Bottom Layer w10: R23.2@3205.04,1428.35 3208.55,1431.86 J20.1@3208.55,1515.6
NetJ22_1: J22.1 R25.2 U4.C1 | length 1527.5
  Top Layer w10: v1@2953.46,1687.75 U4.C1@2953.46,1705.65 ; R25.2@3195.78,3068.74 3226.99,3037.52 J22.1@3226.99,2862.07
  Layer 4 w10: v1@2952.33,1685.59 2952.33,1730.53 3062.9,1842.13 3062.9,2579.94 3226.99,2744.03 J22.1@3226.99,2862.07
  other v1: 2953.44,1687.73
NetR19_1: R19.1 U4.A2 | length 65.3
  Top Layer w10: U4.A2@2969.21,1737.15 3002.69,1737.15 R19.1@3025.22,1759.68
NetR20_1: R20.1 U4.B2 | length 65
  Top Layer w10: U4.B2@2969.21,1721.4 3003.5,1721.4 R20.1@3025.22,1699.68
NR/SS_1: C9.2 C10.1 U1.8 | length 159.4
  Top Layer w10: U1.8@2640.06,1350.77 2660.03,1330.8 v1(2681.36,1330.8)
  Bottom Layer w10: v1(2681.36,1330.8) 2703.1,1352.54 C10.1@2782.18,1352.54
NR/SS_2: C13.2 C14.1 U2.8 | length 161.5
  Top Layer w10: U2.8@2642.26,1082.79 2651.48,1082.79 v1(2681.05,1053.22) C13.2@2681.88,1052.39
  Bottom Layer w10: v1(2681.05,1053.22) 2712.19,1022.08 C14.1@2777.45,1022.08
NR/SS_3: C17.2 C18.1 U3.8 | length 168.2
  Top Layer w10: v1(2656.63,775.88) 2640.41,792.1 U3.8@2640.41,799.97 2698.58,799.97 C17.2@2705.87,807.26
  Bottom Layer w10: v1(2656.63,775.88) 2673.56,758.95 C18.1@2673.56,714
PG_1: R2.2 TP1.1 U1.14 | length 2588.4
  Top Layer w10: U1.14@2620.78,1478.13 2620.38,1478.13 2620.38,1516.44 R2.2@2624.47,1520.53
  Layer 4 w10: v1@2623.5,1520.99 2650.14,1547.63 2675.23,1547.63 2692.81,1530.05 2692.81,1509.07 3763.37,447.86 v1(3763.37,-480)
  other v1: 2623.37,1523.27
PG_2: R5.2 TP2.1 U2.14 | length 2683
  Top Layer w10: U2.14@2623.52,1210.15 U2.14@2622.57,1210.15 2622.57,1250.65 R5.2@2623.51,1251.59
  Layer 4 w10: v1(2623.1,1251.6) 2593.04,1281.65 2593.04,1326.03 2625.06,1358.05 2743.1,1358.05 3690.8,410.35 3690.8,-543.68 v1(3758.49,-611.36)
PG_3: R8.2 TP3.1 U3.14 | length 2958.9
  Top Layer w10: R8.2@2620.56,969.37 2620.72,969.21 U3.14@2620.72,927.34 ; U3.14@2621.41,928.03 U3.14@2620.72,927.34 ; U3.14@2621.67,927.34 U3.14@2620.72,927.34
  Layer 4 w10: v1(2619.89,969.61) 2672.89,916.61 2672.89,819.46 2668.97,815.54 2625.06,815.54 2593.8,784.28 2593.8,749.26 2587,742.47 2587,401.61 2644.81,343.8 3567,343.8 3660.8,250 3660.8,-738.86 v1(3758.49,-836.54)
REF: R6.2 R10.2 U1.7 U2.7 U3.7 | length 804
  Top Layer w10: U1.7@2620.38,1350.77 2620.38,1326.03 v1(2628.23,1318.08) ; v1(2620.57,779.27) 2620.57,799.82 U3.7@2620.72,799.97 ; U2.7@2622.57,1082.79 2623.32,1082.04 v1(2623.32,1067.53)
  Layer 4 w10: v1(2613.05,720.1) 2613.05,745.69 2620.57,753.2 v1(2620.57,779.27) 2641.21,799.91 2675.44,799.91 2689.51,813.98 2689.51,1001.22 2623.32,1067.4 v1(2623.32,1067.53) 2648.02,1092.23 2661.77,1092.23 2681.99,1112.44 2681.99,1264.32 v1(2628.23,1318.08)
VDD: C20.1 C21.1 C22.2 C23.2 J21.1 J21.2 U4.A1 | length 246.5
  Top Layer w10: C21.1@2899.21,1754.15 2916.21,1737.15 U4.A1@2953.46,1737.15
  Top Layer w20: C22.2@2728.4,1861.33 2728.73,1816.13 ; C22.2@2729.47,1862.89 v1(2824.28,1862.15) ; C23.2@2823.96,1862.89 2824.28,1817.69
  other v1: 2899.16,1752.86 2728.14,1862.15
VIN: C26.1 C27.2 C28.2 C29.2 C30.2 C31.2 C32.1 C33.1 C34.1 C35.1 C36.1 C37.1 C38.2 C39.1 C40.1 C41.1 C42.1 C43.1 C44.1 C45.1 C46.2 C47.2 C48.2 C49.2 C50.1 C51.1 C52.1 C53.1 C54.1 C55.1 C56.2 C57.2 C58.1 C59.1 C60.1 C61.1 C62.1 C63.1 C64.1 C65.2 C66.2 C67.2 C68.2 C69.2 C70.1 C71.1 C72.1 C73.1 C74.1 C75.1 C76.2 C77.1 C78.1 C79.1 C80.1 C81.1 C82.1 J3.3 J5.1 J7.1 J10.3 J13.3 J16.3 J27.1 J27.2 J28.1 J28.3 J30.2 U1.1 U1.2 U1.3 U1.4 U2.1 U2.2 U2.3 U2.4 U3.1 U3.2 U3.3 U3.4 | length 5899.9
  Top Layer w10: C80.1@630.13,314.26 C67.2@630.75,217.18 ; 802.2,314.33 900,314.25 ; 807.79,1967.15 902.58,1966.67 ; C58.1@1564.06,1306.98 C59.1@1682.75,1306.53 ; C50.1@1579.47,986.35 C51.1@1674.81,985.95 ; 1591.93,1332.62 1660.06,1332.6 ; 1598.04,931.23 1654.55,931.23 ; C53.1@1836.06,955.25 C46.2@1892.57,955.25 ; C53.1@1839.5,960.86 C49.2@1839.5,1017.37 ; C46.2@1921.93,960.45 C52.1@1978.45,960.45 ; 2282.19,387.63 2282.27,485.43 ; C36.1@2296.6,2030.83 C31.2@2353.11,2030.83 ; C35.1@2302.01,1597.74 C30.2@2366.61,1597.74 ; C70.1@2309.37,394.87 C71.1@2309.45,492.67 ; C74.1@2309.56,228.65 C69.2@2366.07,228.65 ; C33.1@2312.14,1859.15 C32.1@2312.75,1762.07 ; C27.2@2316.81,1523.67 C34.1@2317.43,1426.59 ; 2332.47,432.69 C71.1@2332.47,489.2 ; C33.1@2353.48,1875.05 2354.1,1777.97 ; 2388.11,2248.24 2388.97,2249.1 J3.3@2388.97,2331.8 ; U1.1@2552.81,1449.69 2552.81,1465.58 2539.32,1479.07 2539.32,1505.53 2552.79,1519 2552.79,1549.85 2566.63,1563.69 J5.1@2566.63,1641.34 2566.63,1876.83 2670.37,1980.56 J7.1@2670.37,2065.11
  Layer 4 w10: v1@2299.47,1326.03 2299.47,2514.88 J10.3@2391.25,2606.66 ; C68.2@2367.12,663.01 2266.54,763.59 2266.54,2751.38 J16.3@2388.97,2873.82
  other v1: 1258.92,36.13 1306.03,35.92 1939.57,36.22 1986.68,36.02 1258.92,142.76 1306.03,142.76 1940.42,147.94 2300.42,1327.94 1254.15,2115.33 1300.28,2115.33 1934.67,2120.51 1254.02,2227.25 1301.13,2227.04 1934.67,2227.34 1981.78,2227.14
VOUT: C1.2 C4.1 C5.1 J1.1 J4.1 J11.1 J18.1 R1.2 R4.2 R6.1 R7.2 R12.2 R13.2 R14.2 R15.2 R16.2 R17.2 | length 2197.4
  Top Layer w10: R6.1@2613.05,672.86 2758.81,527.1 J4.1@2894.74,527.1 2894.74,923.73 2889.44,929.04 ; J1.1@2777.45,1629.12 2777.45,1531.87 2827.26,1482.07 2864.73,1482.07 R1.2@2865.7,1483.04 ; R7.2@2867.08,928.98 R7.2@2867.08,950.79 ; 2875.89,1406.99 R1.2@2875.89,1444.47 ; R4.2@2877.37,1249.06 2877.37,1286.54 ; R17.2@3211.68,1859.9 R13.2@3716.81,1857.97
  Top Layer w20: R7.2@2863.51,973.2 2911.47,973.32 ; R7.2@2863.78,928.97 2867.08,928.98 2867.14,928.98 2889.44,929.04 2911.74,929.09 ; R1.2@2865.7,1483.04 2913.66,1483.16 ; R1.2@2870.47,1440.4 2918.43,1440.52 ; R4.2@2871.41,1246.55 2919.37,1246.67 ; R4.2@2875.79,1202.62 2923.75,1202.74 ; R1.2@2877.47,1474.92 C5.1@2944.65,1474.42 ; C5.1@2972.43,1468.82 2972.55,1420.86 ; C5.1@2982.95,1475.99 C4.1@3030.91,1476.11 ; C4.1@3056.58,1468.77 R12.2@3104.54,1468.89 ; C4.1@3057.26,1473.53 3057.38,1425.57 ; 3059.98,1398.67 R12.2@3107.94,1398.79 ; 3064.42,1374.18 R12.2@3112.38,1374.3
  other v1: 3124.78,446.9 3695.92,446.9 3880,461.63 2865.69,948.9 3805.94,986.77 3912.57,986.77 3805.94,1033.87 3912.77,1033.87 2862.44,1200.31 2864.25,1459.93 2971.1,1475.59 3912.47,1667.42 3800.76,1668.27 3912.68,1714.52 3474.99,1861.78 3602.95,1861.78 3729.79,1861.78 3350.79,1865.72 3449,2288.83
pads on no net: FID1.1 FID2.1 FID3.1 FID4.1 FID5.1 FID6.1 FID7.1 FID8.1 FID9.1 FID10.1 R11.1 R11.2 SH-J1.0 SH-J2.0 SH-J3.0 SH-J4.0

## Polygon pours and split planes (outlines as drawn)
VIN on Top Layer "Top Layer-VIN_2" (solid, remove dead copper, pour order 120): 1013.76,917.33 2019.66,917.33 2102.2,999.87 2553.19,999.87 2553.19,1295.59 2602.86,1345.26 763.47,1345.26 543.42,1125.21 0.8,1125.21 0.8,600 1009.95,600 1009.95,913.52
GND on Top Layer "Layer 2-GND 1" (solid, remove dead copper, pour order 99): 1283.21,695.05 1951.48,695.05 1952.41,694.13 1952.41,203.1 2269.29,203.1 2271.5,205.3 2271.5,994.16 2096.49,994.16 2019.66,917.33 1282.52,917.33 1282.19,917.65 1282.19,917.33 1282.01,917.14 1009.23,917.14 1009.23,600.72 1009.95,600 0.8,600 0.8,328.03 1283.21,328.03
NetJ18_2 on Top Layer "TOP_LAYER_NETJ18_2_P107" (solid, remove dead copper, pour order 107): 3789.21,1792.24 3162.64,1792.24 3162.64,1514.62 3150.31,1502.29 3150.31,1198.46 3253.64,1198.46 3253.64,1679.33 3788.47,1679.33 3788.55,1679.25 3789.21,1679.91
VOUT on Top Layer "Top Layer-VOUT" (solid, remove dead copper, pour order 105): 3945.01,403.89 3948.89,400.01 3949.77,400.89 3949.77,982.5 3950.93,983.67 3950.93,1745.1 3951.2,1745.36 3951.2,2345.92 3173.07,2345.92 3173.07,1792.24 3773.55,1792.24 3773.55,1008.38 3255.3,1008.38 3253.64,1010.04 3253.64,1213.87 3153.61,1213.87 3150.31,1217.18 3150.31,1499.37 3101.19,1499.37 3084.12,1516.44 2920.86,1516.44 2920.86,1519.03 2898.55,1541.34 2850.83,1541.34 2850.84,1491.33 2850.84,914.38 2905.58,914.38 2905.58,688.01 3006.98,688.01 3013.39,681.61 3013.39,403.89
VIN on Top Layer "Top Layer-VIN_1 1" (solid, remove dead copper, pour order 103): 2017.49,2090.42 2020.97,2086.94 2265.63,2086.94 2265.63,1352.26 2266.54,1351.35 2282.86,1367.67 2579.04,1367.67 2579.04,1455.1 2522.19,1455.1 2522.19,2269.11 2018.19,2269.11 2017.49,2269.11
VIN on Top Layer "Top Layer-VIN_3 1" (solid, remove dead copper, pour order 20): 2268.55,-290.07 2544.44,-289.71 2544.44,975.78 2268.55,975.78 2268.55,207.9 1951.67,207.9 1949.46,205.7 1949.46,-289.71 2268.55,-289.71
GND on Top Layer "Top Layer-GND 1" (solid, remove dead copper, pour order 96): 1289.31,1346.08 2266.54,1346.08 2266.54,2084.74 2268.74,2086.94 1957.49,2086.94 1957.49,1568.21 1289.22,1568.21 1289.22,1950.91 1286.66,1953.47 0.8,1953.47 0.8,1125.21 543.42,1125.21 543.42,1127.21 762.39,1346.18 1289.22,1346.18
VIN on Top Layer "Top Layer-VIN_1" (solid, remove dead copper, pour order 17): 0.75,1951.83 1286.65,1951.83 1288.29,1953.47 1288.29,2089.86 2022.58,2089.86 2022.58,2262.72 2022.39,2262.92 1288.29,2262.92 1288.29,2269.37 212,2269.37 104.69,2269.94 0.75,2269.94
GND on Top Layer "Top Layer-GND 2" (solid, remove dead copper, pour order 95): 3951.2,2345.92 3953.12,2347.84 3953.12,3335.73 3948.7,3331.31 3088.41,3331.31 3088.41,3156.28 3050.8,3118.68 3050.8,2585.74 3049.74,2584.68 2758.79,2584.68 2758.79,3331.31 2754.2,3335.89 2243.17,3335.89 2243.17,2269.03 2243.25,2269.11 2549.47,2269.11 2549.47,1752.74 2548.91,1752.19 2549.72,1751.38 2556.99,1751.38 2556.99,1541.34 2898.55,1541.34 2920.86,1519.03 2920.86,1516.44 3087.18,1516.44 3104.25,1499.37 3171.96,1499.37 3168.55,1502.78 3168.55,1676.58 3014,1676.58 3014,1737.15 2877.55,1737.15 2877.55,1754.15 2862.87,1768.84 2670.37,1768.84 2670.37,1902.61 2884.77,1902.61 2884.77,1829.22 2919.71,1794.29 3058.36,1794.29 3064.42,1788.23 3161.11,1884.91 3173.07,1884.91 3173.07,2345.92
GND on Top Layer "TOP_LAYER_GND_P093" (solid, remove dead copper, pour order 93): 2674.74,1096.18 2877.71,1096.18 2879.73,1094.16 2879.73,998.43 2608.51,998.43 2605.94,1001 2605.94,1047.12 2662.73,1047.12 2676.56,1060.95 2674.74,1062.78
VIN on Top Layer "Top Layer-VIN_3" (solid, remove dead copper, pour order 19): 0,0 1283.03,0 1283.21,0.18 1283.21,0.35 2022.43,0.35 2022.43,168.41 2017.44,173.4 1283.21,173.4 1283.21,328.03 0,328.03
GND on Top Layer "TOP_LAYER_GND_P079" (solid, remove dead copper, pour order 79): 3946.77,-1075.49 2840.11,-1075.49 2840,-1075.38 2840,-923.59 2966.86,-796.73 2966.86,-299.22 2549.93,-299.22 2543.2,-292.49 2543.2,828.07 2650.17,828.07 2848.36,828.07 2850.18,829.89 3008.3,671.77 3008.3,401.87 3947.03,401.87 3948.89,400.01 3946.77,397.88
VDD on Top Layer "TOP_LAYER_VDD_P072" (solid, remove dead copper, pour order 72): 2919.71,1744.31 2919.71,1794.29 2884.77,1829.22 2884.77,1905.97 2670.37,1905.97 2670.37,1768.84 2862.87,1768.84 2887.39,1744.31
VDD on Top Layer "TOP_LAYER_VDD_P065" (solid, remove dead copper, pour order 65): 2758.79,3331.31 3088.41,3331.31 3088.41,3156.28 3050.8,3118.68 3050.8,2590.15 3056.27,2584.68 2758.79,2584.68
BIAS on Top Layer "TOP_LAYER_BIAS_P062" (solid, remove dead copper, pour order 62): 2967.78,-415.32 2966.13,-413.68 2966.13,-797.45 2840,-923.59 2840,-1075.38 2236.87,-1075.38 2236.81,-1075.32 2236.81,-600 2354,-482.81 2354,-299.22 2966.86,-299.22
VIN on Layer 2 "Layer 2-VIN" (solid, remove dead copper, pour order 154): 0,0 1283.03,0 1283.21,0.18 1283.21,0.35 2022.43,0.35 2022.43,168.41 2017.44,173.4 1283.21,173.4 1283.21,328.03 1283.21,917.33 2019.66,917.33 2102.2,999.87 2451.36,999.87 2451.36,1345.26 1279.18,1345.26 1279.18,2089.86 2010.14,2089.86 2010.14,2259.4 2013.47,2262.72 2013.28,2262.92 1279.18,2262.92 1279.18,2269.37 202.89,2269.37 95.58,2269.94 -8.36,2269.94 -8.36,1341.74 0.8,1341.74 0.8,328.03 0,328.03
GND on Layer 2 "Top Layer-GND" (solid, remove dead copper, pour order 141): 1280.37,695.18 1948.64,695.18 1949.57,694.26 1949.57,192.87 2267.69,192.87 2268.65,193.84 2268.65,994.28 2093.65,994.28 2016.81,917.45 1279.68,917.45 1279.35,917.78 1279.35,917.45 1279.17,917.27 1279.17,328.16 1280.37,328.16
BIAS on Layer 2 "Layer 2-BIAS" (solid, remove dead copper, pour order 151): 2236.81,-1075.32 2236.87,-1075.38 2840,-1075.38 2840,-923.59 2966.13,-797.45 2966.13,-413.68 2967.78,-415.32 2966.86,-299.22 2682.6,-299.22 2682.6,1555.75 2461.79,1555.75 2459.56,-299.22 2354,-299.22 2354,-482.81 2236.81,-600
NetJ18_2 on Layer 2 "LAYER_2_NETJ18_2_P150" (solid, remove dead copper, pour order 150): 3788.07,1793.37 3149.17,1793.37 3149.17,1503.43 3149.17,1199.6 3252.5,1199.6 3252.5,1680.47 3787.33,1680.47 3787.41,1680.39 3788.07,1681.05
VOUT on Layer 2 "Layer 2-VOUT" (solid, remove dead copper, pour order 149): 3945.01,403.89 3948.89,400.01 3949.77,400.89 3949.77,982.5 3950.93,983.67 3950.93,1745.1 3951.2,1745.36 3951.2,2345.92 3173.07,2345.92 3173.07,1792.24 3773.55,1792.24 3773.55,1008.38 3255.3,1008.38 3253.64,1010.04 3253.64,1213.87 3153.61,1213.87 3150.31,1217.18 3150.31,1499.37 3101.19,1499.37 3084.12,1516.44 2920.86,1516.44 2920.86,1519.03 2898.55,1541.34 2828.96,1541.34 2828.96,1499.37 2842.79,1499.37 2850.84,1491.32 2850.84,914.38 2905.58,914.38 2905.58,688.01 3006.98,688.01 3013.39,681.61 3013.39,403.89
GND on Layer 2 "LAYER_2_GND_P145" (solid, remove dead copper, pour order 145): 2243.17,3335.89 2243.17,2279.31 2446.33,2279.31 2445.86,2278.85 2445.86,1558.26 2888.43,1558.26 2931.1,1515.59 2931.95,1516.44 3084.12,1516.44 3101.19,1499.37 3104.61,1502.78 3149.17,1502.78 3149.17,1772.98 3173.07,1796.88 3173.07,2345.92 3951.2,2345.92 3953.12,2347.84 3953.12,3335.73 2993.18,3335.73 3000.72,3328.19 3000.72,1728.23 2637.43,1728.23 2635.52,1730.14 2635.78,1730.41 2635.78,3335.89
